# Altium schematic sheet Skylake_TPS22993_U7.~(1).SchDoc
size 431 x 279 mm; Date: Not shown in title block; ApprovedBy: Not shown in title block; CheckedBy: Not shown in title block; Author: Not shown in title block; CompanyName: Not shown in title block; Engineer: Not shown in title block; Organization: Not shown in title block; Address1: Not shown in title block; Address2: Not shown in title block; Address3: Not shown in title block; Address4: Not shown in title block; DocumentNumber: 1; Revision: Use project parameter SCH_Rev; SheetNumber: 4; SheetTotal: 9; PageSetup: Record=PageOptions|CenterHorizontal=True|CenterVertical=True|PrintScale=1.00|XCorrection=1.00|YCorrection=1.00|PrintKind=0|BorderSize=5000000|LeftOffset=0|BottomOffset=0|Orientation=2|PaperLength=1000|PaperWidth=1000|Scale=100|PaperSource=15|PrintQuality=600|MediaType=1|DitherType=10|PaperKind=Letter|PrintScaleMode=1
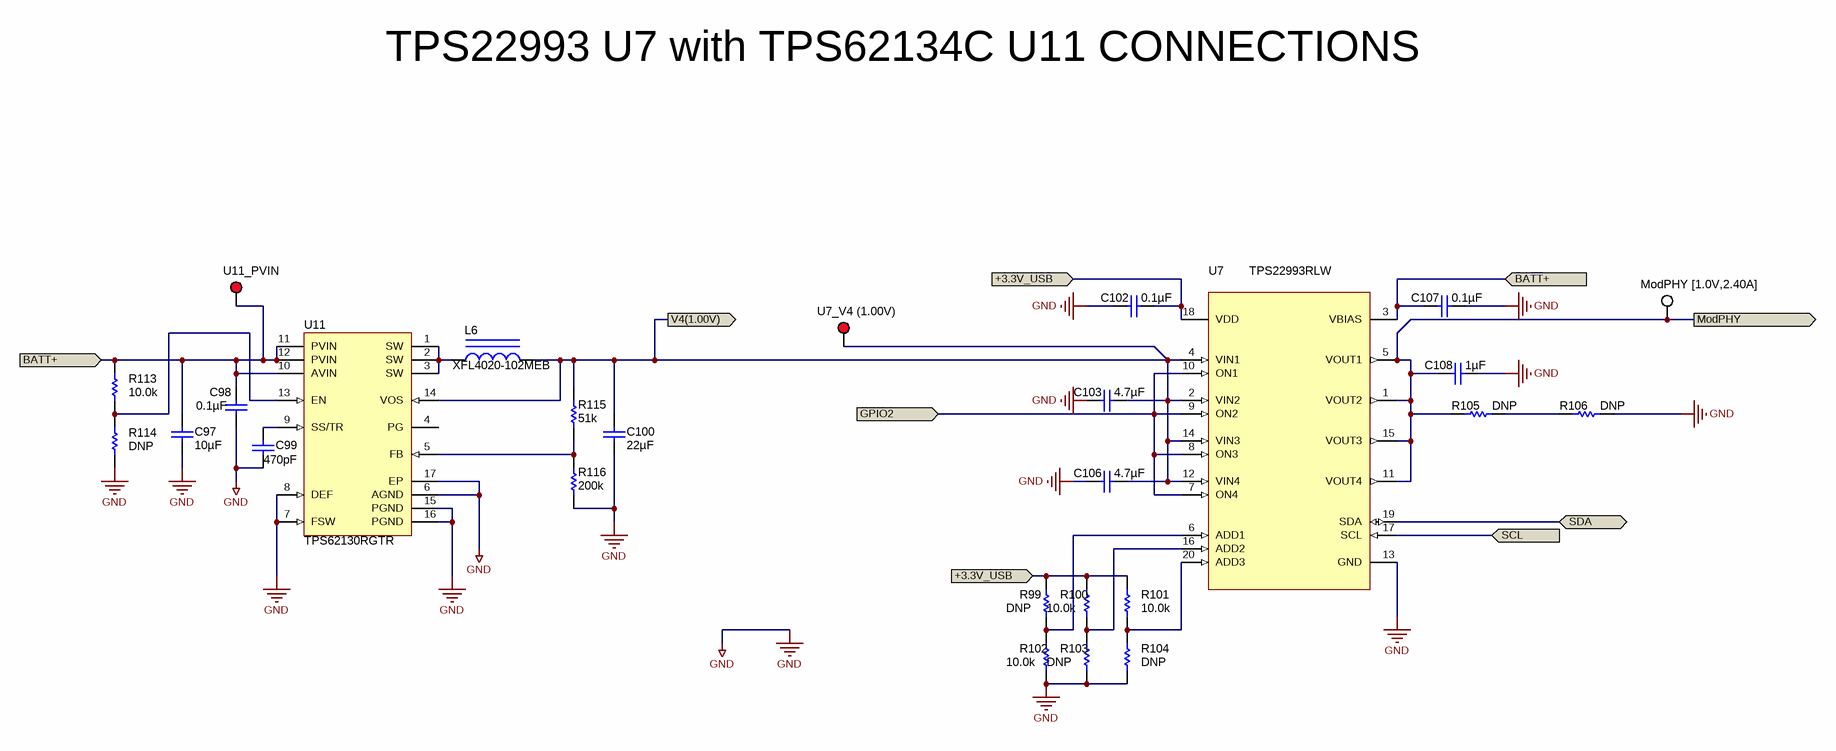
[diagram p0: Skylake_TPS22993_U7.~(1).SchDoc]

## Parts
C97  ValueDisplayed: 10µF  [0805_HV]  (hidden comment: C2012JB1V106K085AC)
C98  ValueDisplayed: 0.1µF  [0805_HV]  (hidden comment: 08055C104JAT2A)
C99  ValueDisplayed: 470pF  [0603]  (hidden comment: C0603C471K5RACTU)
C100  ValueDisplayed: 22µF  [0805_HV]  (hidden comment: LMK212BJ226MG-T)
C102  ValueDisplayed: 0.1µF  [0603]  (hidden comment: C0603C104K8RACTU)
C103  ValueDisplayed: 4.7µF  [0603]  (hidden comment: GRM188R60J475KE19D)
C106  ValueDisplayed: 4.7µF  [0603]  (hidden comment: GRM188R60J475KE19D)
C107  ValueDisplayed: 0.1µF  [0805_HV]  (hidden comment: GMK212BJ104KGHT)
C108  ValueDisplayed: 1µF  [0603]  (hidden comment: C0603C105K8PACTU)
L6  XFL4020-102MEB  [XFL4020]
ModPHY_[1.0V,2.40A]  5007  [Keystone5007]  (value not drawn)
R99  value DNP  [0402]  (hidden comment: CRCW040210K0FKED)
R100  value 10.0k  [0402]  (hidden comment: CRCW040210K0FKED)
R101  value 10.0k  [0402]  (hidden comment: CRCW040210K0FKED)
R102  value 10.0k  [0402]  (hidden comment: CRCW040210K0FKED)
R103  value DNP  [0402]  (hidden comment: CRCW040210K0FKED)
R104  value DNP  [0402]  (hidden comment: CRCW040210K0FKED)
R105  value DNP  [2512M]  (hidden comment: RLP73K3AR20JTE)
R106  value DNP  [2512M]  (hidden comment: RLP73K3AR22JTE)
R113  value 10.0k  [0402]  (hidden comment: CRCW040210K0FKED)
R114  value DNP  [0402]  (hidden comment: CRCW040210K0FKED)
R115  value 51k  [0603]  (hidden comment: CRCW060351K0JNEA)
R116  value 200k  [0603]  (hidden comment: CRCW0603200KFKEA)
U7  TPS22993RLW  [RLW0020A]
U7_V4_(1.00V)  5005  [Keystone5005]  (value not drawn)
U11  TPS62130RGTR  [RGT0016C]
U11_PVIN  5005  [Keystone5005]  (value not drawn)

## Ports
+3.3V_USB (in), BATT+ (in), GPIO2 (in), ModPHY (out), SCL (in), SDA (bidir), V4(1.00V) (out)

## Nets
GND: C97.2 C98.2 C99.2 C100.2 C102.2 C103.2 C106.2 C107.1 C108.1 R102.1 R103.1 R104.1 R106.2 R114.1 R116.1 U7.13(GND) U11.6(AGND) U11.7(FSW) U11.8(DEF) U11.15(PGND) U11.16(PGND) U11.17(EP)
+3.3V_USB: C102.1 R99.2 R100.2 R101.2 U7.18(VDD) ; port +3.3V_USB
BATT+: C97.1 C98.1 C107.2 R113.2 U7.3(VBIAS) U11.10(AVIN) U11.11(PVIN) U11.12(PVIN) U11_PVIN.1 ; port BATT+
GPIO2: U7.7(ON4) U7.8(ON3) U7.9(ON2) U7.10(ON1) ; port GPIO2
ModPHY: C108.2 ModPHY_[1.0V,2.40A].1 R105.1 U7.1(VOUT2) U7.5(VOUT1) U7.11(VOUT4) U7.15(VOUT3) ; port ModPHY
SCL: U7.17(SCL) ; port SCL
SDA: U7.19(SDA) ; port SDA
V4(1.00V): C100.1 C103.1 C106.1 L6.2 R115.2 U7.2(VIN2) U7.4(VIN1) U7.12(VIN4) U7.14(VIN3) U7_V4_(1.00V).1 U11.14(VOS) ; port V4(1.00V)
NetC99_1: C99.1 U11.9(SS/TR)
NetL6_1: L6.1 U11.1(SW) U11.2(SW) U11.3(SW)
NetR99_1: R99.1 R102.2 U7.6(ADD1)
NetR100_1: R100.1 R103.2 U7.16(ADD2)
NetR101_1: R101.1 R104.2 U7.20(ADD3)
NetR105_2: R105.2 R106.1
NetR113_1: R113.1 R114.2 U11.13(EN)
NetR115_1: R115.1 R116.2 U11.5(FB)

Not connected (* = marked no-connect by the designer): U11 4(PG)

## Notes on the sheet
- TPS22993 U7 with TPS62134C U11 CONNECTIONS

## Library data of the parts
C97 = GRM21BR61E226ME44: CAP, CERM, 10uF, 35V, +/-10%, X5R, 0805; Manufacturer: TDK Corporation; Polarized: N; CompType: Capacitor; U/M: EA; Cap_F: 0.000022; Tolerance_%: 20; Value1: Unknown; VDC_V: 35; TaMin_C: -55; TaMax_C: 85; Cap_Case: 0805
C98 = 08055C104JAT2A: CAP, CERM, 0.1uF, 50V, +/-5%, X7R, 0805; Manufacturer: AVX; Polarized: N; CompType: Capacitor; U/M: EA; Cap_F: 0.0000001; Tolerance_%: 5; ESR_Ohm: 0.024; Value1: 0.024 ohm; VDC_V: 50; TaMin_C: -55; TaMax_C: 125; Cap_Case: 0805
C99 = C0603C471K5RACTU: CAP, CERM, 470pF, 50V, +/-10%, X7R, 0603; Manufacturer: Kemet; Polarized: N; CompType: Capacitor; U/M: EA; Cap_F: 0.00000000047; Tolerance_%: 10; Value1: Unknown; VDC_V: 50; TaMin_C: -55; TaMax_C: 125
C100 = LMK212BJ226MG-T: CAP, CERM, 22uF, 10V, +/-20%, X5R, 0805; Manufacturer: Taiyo Yuden; Polarized: N; CompType: Capacitor; U/M: EA; Cap_F: 0.000022; Tolerance_%: 20; Value1: Unknown; VDC_V: 10; TaMin_C: -55; TaMax_C: 85; Cap_Case: 0805
C102 = GRM188R71C104KA01D: CAP, CERM, 0.1uF, 10V, +/-10%, X7R, 0603; Manufacturer: Kemet; Polarized: N; CompType: Capacitor; U/M: EA; Cap_F: 0.0000001; Tolerance_%: 10; Value1: Unknown; TaMin_C: -55; TaMax_C: 125
C103 C106 = GRM188R60J475KE19D: CAP, CERM, 4.7uF, 6.3V, +/-10%, X5R, 0603; Manufacturer: MuRata; Polarized: N; CompType: Capacitor; U/M: EA; Cap_F: 0.0000047; Tolerance_%: 10; ESR_Ohm: 0.005; Value1: 0.005 ohm; VDC_V: 6.3; IRMS_A: 2; TaMin_C: -55; TaMax_C: 85
C107 = GRM21BR61E226ME44: CAP, CERM, 0.1uF, 35V, +/-20%, X5R, 0805; Manufacturer: Taiyo Yuden; Polarized: N; CompType: Capacitor; U/M: EA; Cap_F: 0.000022; Tolerance_%: 20; Value1: Unknown; VDC_V: 35; TaMin_C: -55; TaMax_C: 85; Cap_Case: 0805
C108 = C0603C105K8PACTU: CAP, CERM, 1uF, 10V, +/-10%, X5R, 0603; Manufacturer: Kemet; Polarized: N; CompType: Capacitor; U/M: EA; Cap_F: 0.000001; Tolerance_%: 10; Value1: Unknown; TaMin_C: -55; TaMax_C: 85
L6 = XFL4020-102MEB: Inductor, Shielded, Composite, 1uH, 5.4A, 0.01 ohm, SMD; Manufacturer: Coilcraft; Ind_H: 1.0E-6; ValueDisplayed: 1µH; Imax_A: 5.4; Irms: 11A @ 40C rise; Isat: 5.4A @ 30% inductance drop; DCR_ohm: 0.01; U/M: EA
ModPHY_[1.0V,2.40A] = 5007: Test Point, Compact, White, TH; Manufacturer: Keystone; CompType: Test Point Loop; U/M: EA
R99 R103 R104 R114 = CRCW040210K0FKED: RES, DNP, 1%, 0.063W, 0402; Manufacturer: Vishay-Dale; CompType: Resistor; Res_ohm: 10000; Value_Code: 10k0; Tolerance_%: 1; Power_W: 0.063; VDC_V: 50; TempCo: 100 ppm/C; EIA_Code: E96; U/M: EA
R100-R102 R113 = CRCW040210K0FKED: RES, 10.0k ohm, 1%, 0.063W, 0402; Manufacturer: Vishay-Dale; CompType: Resistor; Res_ohm: 10000; Value_Code: 10k0; Tolerance_%: 1; Power_W: 0.063; VDC_V: 50; TempCo: 100 ppm/C; EIA_Code: E96; U/M: EA
R105 R106 = CRCW25121K10JNEG: RES, DNP, 5%, 2W, 2512; Manufacturer: TE Connectivity; CompType: Resistor; Tolerance_%: 5; Power_W: 1; VDC_V: 500; TempCo: 200 ppm/C; EIA_Code: E24; U/M: EA
R115 = CRCW060351K0JNEA: RES, 51k ohm, 5%, 0.1W, 0603; Manufacturer: Vishay-Dale; CompType: Resistor; Res_ohm: 51000; Value_Code: 51k0; Tolerance_%: 5; Power_W: 0.1; VDC_V: 75; TempCo: 200 ppm/C; EIA_Code: E24; U/M: EA
R116 = CRCW0603200KFKEA: RES, 200k ohm, 1%, 0.1W, 0603; Manufacturer: Vishay-Dale; CompType: Resistor; Res_ohm: 200000; Tolerance_%: 1; Power_W: 0.1; VDC_V: 75; TempCo: 100 ppm/C; EIA_Code: E96; U/M: EA
U7 = TPS22993RLW: Quad Channel Load Switch with GPIO and I2C Control, RLW0020A; Alternate Manufacturer: None; Manufacturer: Texas Instruments; SymbolCreator: a0411947; CompType: IC; U/M: EA
U7_V4_(1.00V) U11_PVIN = 5005: Test Point, Compact, Red, TH; Manufacturer: Keystone; CompType: Test Point Loop; U/M: EA
U11 = TPS62130RGTR: Buck Step Down Regulator with 3 to 17 V Input and 0.9 to 6 V Output, -40 to 85 degC, 16-Pin QFN (RGT), Green (RoHS & no Sb/Br); Manufacturer: Texas Instruments; Alternate Manufacturer: None; Alternate PartNumber: Equivalent; Duty Cycle(Max)(%): 100; Iout(Max)(A): 3; Iq(Typ)(mA): 0.017; Rating: Catalog; Regulated Outputs(#): 1; SubFamily: Step-Down Regulator; Switch Current Limit(Typ)(A): 4.2; Synchronous Rectification: TRUE; Vin(Max)(V): 17; Vout(Max)(V): 6; Vout(Min)(V): 0.9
